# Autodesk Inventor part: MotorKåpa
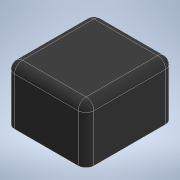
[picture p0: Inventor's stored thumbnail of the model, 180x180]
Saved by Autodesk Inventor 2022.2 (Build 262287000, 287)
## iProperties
Created: 2022-03
Part Number: MotorKåpa
Material: Rubber
Document SubType Name: Modeling
Designer: cl
Density: 0.93 g/cm^3
Appearance: Rubber - Black
Author: cl
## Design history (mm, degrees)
sketch "Sketch1"
  geometry: L1 (-10, 0)-(-90, 0); L2 (-100, -10)-(-100, -100); L3 (-90, -110)-(-10, -110); L4 (0, -100)-(0, -10); A1 r 10 centre (-10, -10) between (0, -10) and (-10, 0); A2 r 10 centre (-10, -100) between (-10, -110) and (0, -100); A3 r 10 centre (-90, -100) between (-100, -100) and (-90, -110); A4 r 10 centre (-90, -10) between (-90, 0) and (-100, -10); 4 further points
  constraints: 8 end point, 8 point on circle, 8 point on line, 8 tangent, 4 centre point, 3 equal radius, 2 parallel, 1 horizontal, 1 perpendicular
  dimensions: "d0" = 100 distance of point (0, -110) point (-100, -110); "d1" = 110 distance of point (-100, -110) point (-100, 0); "d2" = 10 radius of A1
extrude "Extrusion1" new body sketch "Sketch1" distance "d3" = 70; taper "d4" = 0 deg
fillet "Fillet1" dims "d5" = 10
body "Solid1"
